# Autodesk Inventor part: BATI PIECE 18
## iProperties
Created: 2004-11
Part Number: BATI PIECE 18
Document SubType Name: Modeling
Designer: Bruno
Manufacturer: Standard
Standards Organization: Custom
Author: Bruno
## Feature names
1. Base1
